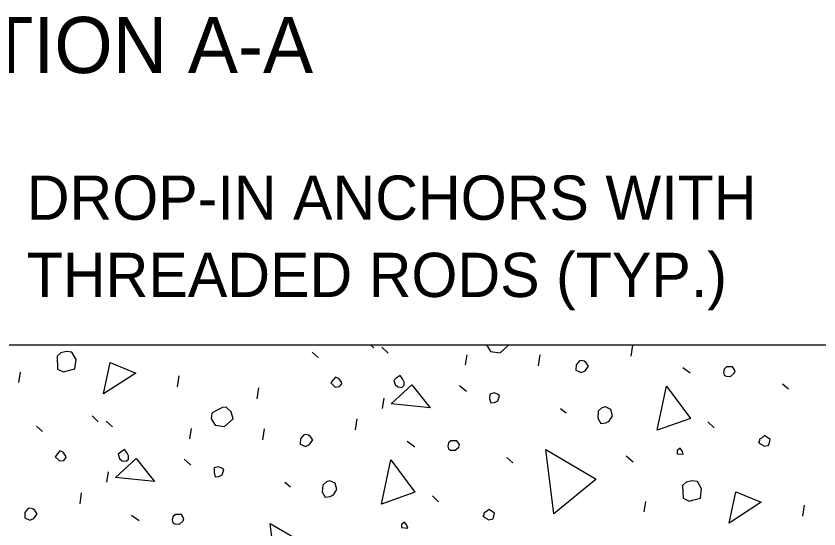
# Model space of a CAD drawing. Extents: x -1660015.2 to -1659984.9, y 2580594.2 to 2580616.7.
# Drawn here: x -1660000.2 to -1659997.457, y 2580603.426 to 2580605.179 of the extents above; entities that cross this region are included whole.
import ezdxf

# ---------------------------------------------------------------- set-up
doc = ezdxf.new("R2010")
doc.units = 0
for name, color, linetype in [('Miscellaneous', 7, 'Continuous'), ('Miscellaneous3', 7, 'Continuous'), ('PlotBorder_dp', 7, 'Continuous'), ('SheetLines_dp', 7, 'Continuous')]:
    doc.layers.add(name, color=color, linetype=linetype)

msp = doc.modelspace()

# ---------------------------------------------------------------- linework, layer by layer
at = {"layer": 'Miscellaneous'}
for p, q in [((-1659998.989, 2580604.056), (-1659998.9777, 2580604.0451)), ((-1659998.9498, 2580604.0473), (-1659998.9289, 2580604.0271)), ((-1659998.0979, 2580604.0168), (-1659998.0925, 2580604.0545)), ((-1659999.1885, 2580604.03), (-1659999.1682, 2580604.0121)), ((-1659998.6644, 2580603.9867), (-1659998.6583, 2580604.0219)), ((-1659998.4151, 2580603.9836), (-1659998.4097, 2580604.0213)), ((-1660000.191, 2580603.927), (-1660000.1849, 2580603.9623)), ((-1659997.922, 2580603.9785), (-1659997.8962, 2580603.9596)), ((-1659999.6486, 2580603.9119), (-1659999.6431, 2580603.9496)), ((-1659999.3762, 2580603.871), (-1659999.3708, 2580603.9087)), ((-1659998.6844, 2580603.9166), (-1659998.6611, 2580603.897)), ((-1659997.5808, 2580603.9224), (-1659997.5605, 2580603.9046)), ((-1659998.9481, 2580603.8382), (-1659998.9421, 2580603.8734)), ((-1659998.3399, 2580603.8381), (-1659998.3202, 2580603.8226)), ((-1659999.9404, 2580603.813), (-1659999.9195, 2580603.7927)), ((-1659999.8916, 2580603.795), (-1659999.8706, 2580603.7747)), ((-1659999.0397, 2580603.7645), (-1659999.0342, 2580603.8021)), ((-1660000.1302, 2580603.7776), (-1660000.1099, 2580603.7598)), ((-1659999.6062, 2580603.7343), (-1659999.6001, 2580603.7696)), ((-1659999.3569, 2580603.7312), (-1659999.3515, 2580603.7689)), ((-1659997.8358, 2580603.792), (-1659997.8148, 2580603.7717)), ((-1659998.8638, 2580603.7262), (-1659998.838, 2580603.7072)), ((-1659999.6262, 2580603.6642), (-1659999.6028, 2580603.6446)), ((-1659998.5226, 2580603.6701), (-1659998.5023, 2580603.6522)), ((-1659998.1152, 2580603.6757), (-1659998.0918, 2580603.6561)), ((-1659999.8899, 2580603.5858), (-1659999.8838, 2580603.6211)), ((-1659999.2817, 2580603.5857), (-1659999.262, 2580603.5703)), ((-1659999.9815, 2580603.5121), (-1659999.976, 2580603.5498)), ((-1659998.7776, 2580603.5396), (-1659998.7566, 2580603.5194)), ((-1659998.0538, 2580603.4851), (-1659998.0477, 2580603.5204)), ((-1659997.5114, 2580603.47), (-1659997.506, 2580603.5077)), ((-1659999.8056, 2580603.4738), (-1659999.7798, 2580603.4549))]:
    msp.add_line(p, q, dxfattribs=at)
for points in [[(-1659998.5922, 2580604.0552), (-1659998.5785, 2580604.033), (-1659998.5462, 2580604.0287), (-1659998.517, 2580604.0546), (-1659998.5173, 2580604.056)], [(-1659998.5921, 2580604.056), (-1659998.5922, 2580604.0552)], [(-1660000.0597, 2580604.0166), (-1660000.0583, 2580603.9729), (-1660000.0375, 2580603.963), (-1660000.0255, 2580603.9662), (-1659999.9989, 2580603.9733), (-1659999.9946, 2580604.0055), (-1660000.009, 2580604.0301), (-1660000.0278, 2580604.0329), (-1660000.0471, 2580604.0277), (-1660000.0597, 2580604.0166)], [(-1659999.9011, 2580603.8882), (-1659999.878, 2580603.9954), (-1659999.7907, 2580603.9592), (-1659999.9011, 2580603.8882)], [(-1659998.2866, 2580603.9869), (-1659998.2869, 2580603.9688), (-1659998.2692, 2580603.9606), (-1659998.2553, 2580603.9669), (-1659998.2441, 2580603.9828), (-1659998.2521, 2580603.9936), (-1659998.2589, 2580603.9995), (-1659998.2699, 2580604.0018), (-1659998.2747, 2580604.0005), (-1659998.2866, 2580603.9869)], [(-1659997.7802, 2580603.9518), (-1659997.7741, 2580603.9483), (-1659997.7583, 2580603.9473), (-1659997.7458, 2580603.9584), (-1659997.7429, 2580603.967), (-1659997.7516, 2580603.9802), (-1659997.7722, 2580603.9798), (-1659997.7806, 2580603.9724), (-1659997.7828, 2580603.9615), (-1659997.7802, 2580603.9518)], [(-1659999.1243, 2580603.9256), (-1659999.1101, 2580603.9112), (-1659999.0949, 2580603.9127), (-1659999.0872, 2580603.9225), (-1659999.0885, 2580603.9274), (-1659999.0972, 2580603.9406), (-1659999.1088, 2580603.9452), (-1659999.1165, 2580603.9354), (-1659999.1243, 2580603.9256)], [(-1659998.9052, 2580603.9195), (-1659998.8954, 2580603.9118), (-1659998.882, 2580603.9102), (-1659998.8737, 2580603.9176), (-1659998.8738, 2580603.9279), (-1659998.8795, 2580603.9394), (-1659998.8876, 2580603.9502), (-1659998.9007, 2580603.9414), (-1659998.9091, 2580603.934), (-1659998.9052, 2580603.9195)], [(-1659998.9187, 2580603.8538), (-1659998.8482, 2580603.9193), (-1659998.7856, 2580603.8403), (-1659998.9187, 2580603.8538)], [(-1659998.0093, 2580603.7636), (-1659997.9773, 2580603.9145), (-1659997.896, 2580603.8043), (-1659998.0093, 2580603.7636)], [(-1659998.5818, 2580603.8716), (-1659998.5779, 2580603.8571), (-1659998.5652, 2580603.8579), (-1659998.5538, 2580603.8636), (-1659998.548, 2580603.8807), (-1659998.5548, 2580603.8866), (-1659998.5664, 2580603.8913), (-1659998.5809, 2580603.8874), (-1659998.5818, 2580603.8716)], [(-1659999.5339, 2580603.8028), (-1659999.5202, 2580603.7806), (-1659999.488, 2580603.7763), (-1659999.4587, 2580603.8023), (-1659999.4652, 2580603.8264), (-1659999.4825, 2580603.8425), (-1659999.4952, 2580603.8417), (-1659999.5156, 2580603.831), (-1659999.5312, 2580603.8217), (-1659999.5339, 2580603.8028)], [(-1659998.2106, 2580603.8287), (-1659998.212, 2580603.8051), (-1659998.202, 2580603.787), (-1659998.1844, 2580603.7892), (-1659998.173, 2580603.7948), (-1659998.1624, 2580603.8132), (-1659998.1682, 2580603.8349), (-1659998.1859, 2580603.8431), (-1659998.198, 2580603.8399), (-1659998.2106, 2580603.8287)], [(-1659999.2284, 2580603.7346), (-1659999.2287, 2580603.7164), (-1659999.211, 2580603.7082), (-1659999.1971, 2580603.7145), (-1659999.1859, 2580603.7305), (-1659999.1939, 2580603.7412), (-1659999.2007, 2580603.7472), (-1659999.2116, 2580603.7494), (-1659999.2165, 2580603.7481), (-1659999.2284, 2580603.7346)], [(-1659997.6611, 2580603.7197), (-1659997.6428, 2580603.7091), (-1659997.6283, 2580603.713), (-1659997.6231, 2580603.7325), (-1659997.6422, 2580603.7455), (-1659997.6505, 2580603.7381), (-1659997.6595, 2580603.7331), (-1659997.6611, 2580603.7197), (-1659997.6624, 2580603.7246)], [(-1659998.722, 2580603.6995), (-1659998.7159, 2580603.6959), (-1659998.7001, 2580603.695), (-1659998.6876, 2580603.7061), (-1659998.6847, 2580603.7146), (-1659998.6934, 2580603.7278), (-1659998.714, 2580603.7275), (-1659998.7224, 2580603.7201), (-1659998.7246, 2580603.7091), (-1659998.722, 2580603.6995)], [(-1660000.066, 2580603.6732), (-1660000.0518, 2580603.6589), (-1660000.0367, 2580603.6604), (-1660000.029, 2580603.6702), (-1660000.0303, 2580603.675), (-1660000.039, 2580603.6882), (-1660000.0506, 2580603.6929), (-1660000.0583, 2580603.683), (-1660000.066, 2580603.6732)], [(-1659999.847, 2580603.6672), (-1659999.8372, 2580603.6595), (-1659999.8238, 2580603.6579), (-1659999.8154, 2580603.6653), (-1659999.8156, 2580603.6756), (-1659999.8213, 2580603.687), (-1659999.8293, 2580603.6978), (-1659999.8425, 2580603.6891), (-1659999.8509, 2580603.6817), (-1659999.847, 2580603.6672)], [(-1659998.3623, 2580603.4775), (-1659998.3903, 2580603.6978), (-1659998.2182, 2580603.5963), (-1659998.3623, 2580603.4775)], [(-1659997.9413, 2580603.6835), (-1659997.92, 2580603.6814), (-1659997.9226, 2580603.6911), (-1659997.9307, 2580603.7019), (-1659997.9415, 2580603.6938), (-1659997.9413, 2580603.6835)], [(-1659999.8605, 2580603.6015), (-1659999.79, 2580603.6669), (-1659999.7274, 2580603.5879), (-1659999.8605, 2580603.6015)], [(-1659998.9511, 2580603.5112), (-1659998.9191, 2580603.6622), (-1659998.8378, 2580603.552), (-1659998.9511, 2580603.5112)], [(-1659999.5236, 2580603.6193), (-1659999.5197, 2580603.6048), (-1659999.507, 2580603.6056), (-1659999.4956, 2580603.6112), (-1659999.4898, 2580603.6283), (-1659999.4965, 2580603.6343), (-1659999.5081, 2580603.6389), (-1659999.5226, 2580603.635), (-1659999.5236, 2580603.6193)], [(-1659999.1523, 2580603.5764), (-1659999.1538, 2580603.5527), (-1659999.1438, 2580603.5347), (-1659999.1262, 2580603.5368), (-1659999.1148, 2580603.5425), (-1659999.1042, 2580603.5608), (-1659999.11, 2580603.5826), (-1659999.1277, 2580603.5908), (-1659999.1398, 2580603.5875), (-1659999.1523, 2580603.5764)], [(-1659997.9225, 2580603.5746), (-1659997.9211, 2580603.531), (-1659997.9004, 2580603.521), (-1659997.8883, 2580603.5243), (-1659997.8617, 2580603.5314), (-1659997.8574, 2580603.5636), (-1659997.8718, 2580603.5882), (-1659997.8906, 2580603.5909), (-1659997.9099, 2580603.5858), (-1659997.9225, 2580603.5746)], [(-1659997.7639, 2580603.4463), (-1659997.7408, 2580603.5534), (-1659997.6535, 2580603.5173), (-1659997.7639, 2580603.4463)], [(-1660000.1702, 2580603.4823), (-1660000.1705, 2580603.4641), (-1660000.1527, 2580603.4559), (-1660000.1389, 2580603.4622), (-1660000.1276, 2580603.4781), (-1660000.1357, 2580603.4889), (-1660000.1425, 2580603.4948), (-1660000.1534, 2580603.4971), (-1660000.1583, 2580603.4958), (-1660000.1702, 2580603.4823)], [(-1659998.6029, 2580603.4674), (-1659998.5845, 2580603.4568), (-1659998.57, 2580603.4607), (-1659998.5649, 2580603.4801), (-1659998.5839, 2580603.4932), (-1659998.5923, 2580603.4858), (-1659998.6013, 2580603.4807), (-1659998.6029, 2580603.4674), (-1659998.6042, 2580603.4722)], [(-1659999.6638, 2580603.4471), (-1659999.6577, 2580603.4436), (-1659999.6419, 2580603.4426), (-1659999.6293, 2580603.4538), (-1659999.6265, 2580603.4623), (-1659999.6352, 2580603.4755), (-1659999.6558, 2580603.4751), (-1659999.6642, 2580603.4677), (-1659999.6664, 2580603.4568), (-1659999.6638, 2580603.4471)], [(-1659999.3041, 2580603.2251), (-1659999.3321, 2580603.4454), (-1659999.16, 2580603.344), (-1659999.3041, 2580603.2251)], [(-1659998.8831, 2580603.4311), (-1659998.8618, 2580603.4291), (-1659998.8644, 2580603.4387), (-1659998.8725, 2580603.4495), (-1659998.8832, 2580603.4414), (-1659998.8831, 2580603.4311)]]:
    msp.add_lwpolyline(points, dxfattribs=at)
at = {"layer": 'Miscellaneous3'}
msp.add_line((-1660001.5583, 2580604.056), (-1659994.5491, 2580604.056), dxfattribs=at)

# ---------------------------------------------------------------- texts
at = {"layer": 'PlotBorder_dp'}
msp.add_text('SECTION A-A', height=0.192, dxfattribs=at).set_placement((-1660000.8255, 2580604.9845))
at = {"layer": 'SheetLines_dp'}
for s, p in [('DROP-IN ANCHORS WITH', (-1660000.1635, 2580604.483)), ('THREADED RODS (TYP.)', (-1660000.1635, 2580604.219))]:
    msp.add_text(s, height=0.1512, dxfattribs=at).set_placement(p)

doc.saveas('drawing.dxf')
